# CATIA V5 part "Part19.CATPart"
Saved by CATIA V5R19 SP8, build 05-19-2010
Part number: Pignon_b
Bounding box of the stored display mesh (mm): x 379.303 to 577.049, y -131.728 to 65.785, z -211.104 to -206.104
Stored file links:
  G:\EU_thinkMotion\CFAO_2010\MMS_groupe1\MMS_groupe1\OK\ppiault\piault\piault_cfao\Part19.CATPart
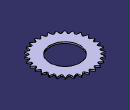
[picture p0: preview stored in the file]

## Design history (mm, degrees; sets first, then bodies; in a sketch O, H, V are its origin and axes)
Body1 (main body)
  Plane1: stored without definition
  Sketch1 on Plane1, origin (0, 0, -211.1043), H (1, 0, 0), V (0, 1, 0)
    point P3 (478.176, -32.9715)
    arc A1 centre (478.176, -32.9715) radius 85 from (550.0443, -78.3582) to (538.9713, -92.3763) ccw
    point P4 (478.176, -32.9715)
    circle A2 centre (478.176, -32.9715) radius 52
    point P5 (556.6478, -94.9567)
    line L1 (550.0443, -78.3582) -> (556.6478, -94.9567)
    line L2 (556.6478, -94.9567) -> (538.9713, -92.3763)
    radius A1 = 85
    radius A2 = 52
    distance P5 P4 = 100
    angle L1 L2 = 60
    concentricity: A2 P3
  Pad1: profile Sketch1, direction (0, 0, 1), length 5
  CircPattern1: of Pad1, instances 31, angular step 12, axis from end face of Pad1
  Fillet1: radius 3, on edge [face of CircPattern1 | face of CircPattern1] (x30)
  Fillet2: radius 1, on edge [face of CircPattern1 | face of CircPattern1] (x30)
